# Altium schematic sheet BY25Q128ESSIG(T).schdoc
size 127 x 101 mm
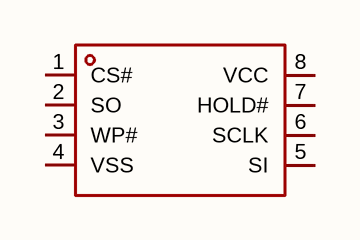
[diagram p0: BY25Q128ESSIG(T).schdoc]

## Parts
U?  by25q128essig(t)  [SOP-8_L5.3-W5.3-P1.27-LS8.0-BL]  (value not drawn)

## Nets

Not connected (* = marked no-connect by the designer): U? 1(CS#) 2(SO) 3(WP#) 4(VSS) 5(SI) 6(SCLK) 7(HOLD#) 8(VCC)

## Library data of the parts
U? = by25q128essig(t): 接口类型:SPI;存储容量:128Mbit;时钟频率(fc):120MHz;; Manufacturer: BOYAMICRO(博雅); AddInBom: yes; ModelId: e456afcfff5840a795bdd4917416584f; ModelName: SOP-8_L5.2-W5.3-H2.1-LS7.9-P1.27; ModelTransform: 311.024,204.724,0,90,0,0,0,0.0005,0; Interface: SPI; Clock Frequency: 120MHz; Voltage - Supply: 2.7V~3.6V; Standby Supply Current: 2uA; Program / Erase Cycles: 100000次; Page Programming Time (Tpp): 700us; Data Retention - TDR (Year): 20年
